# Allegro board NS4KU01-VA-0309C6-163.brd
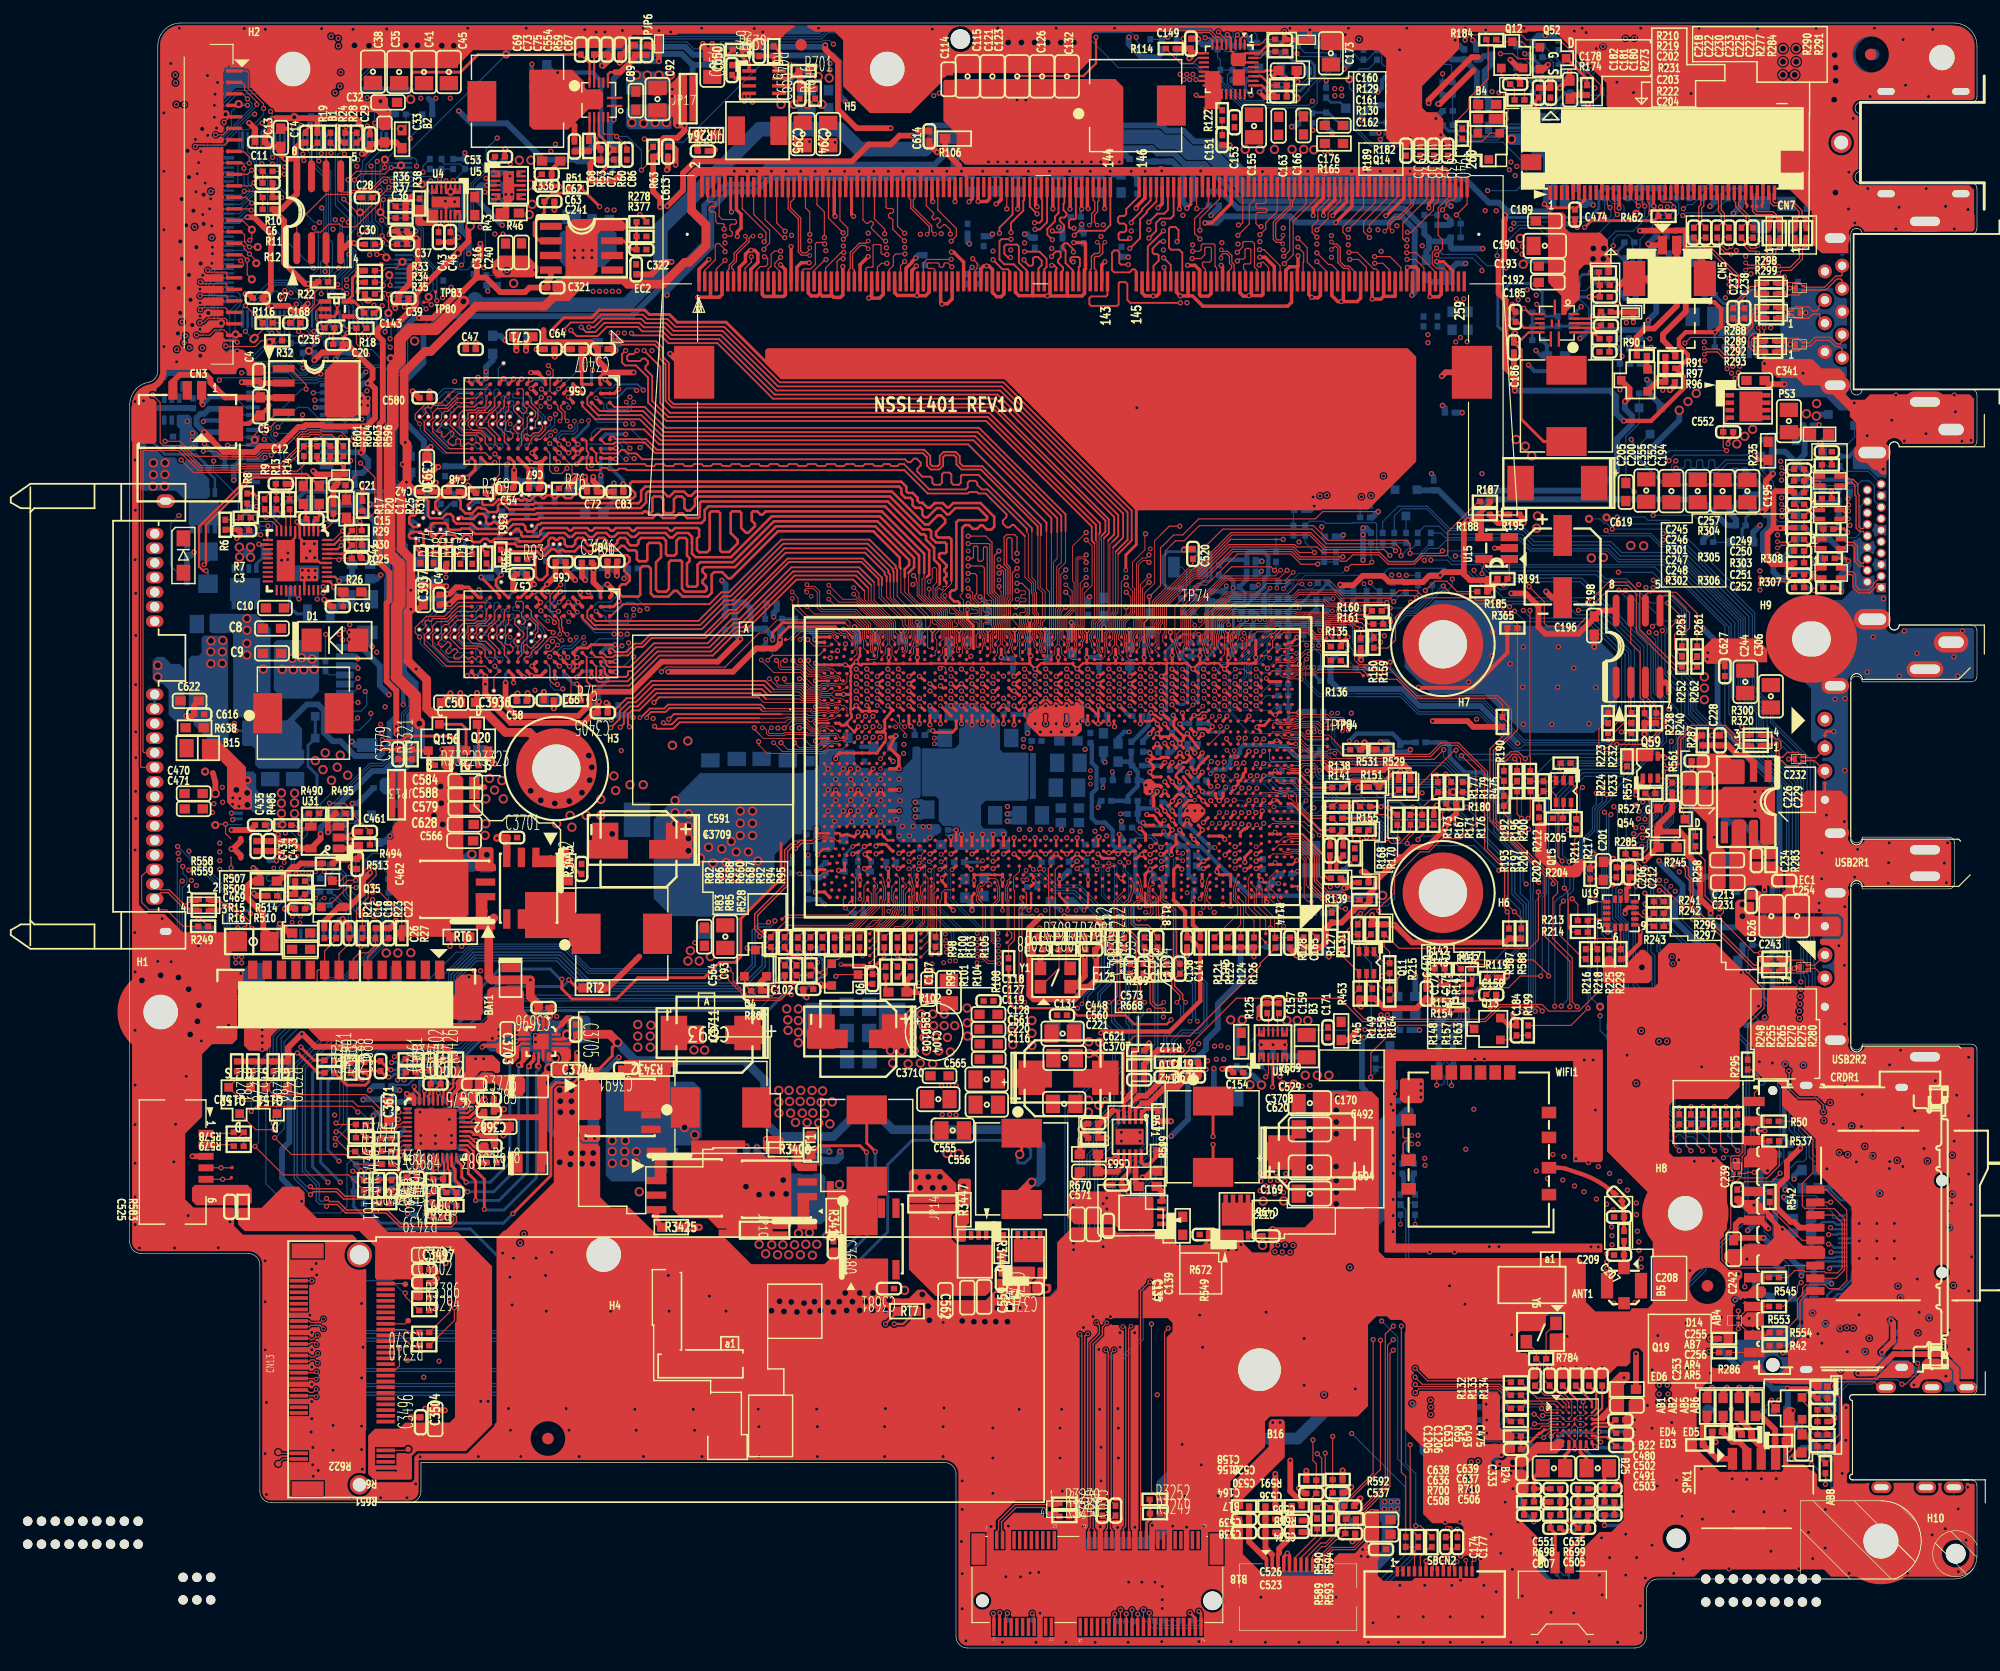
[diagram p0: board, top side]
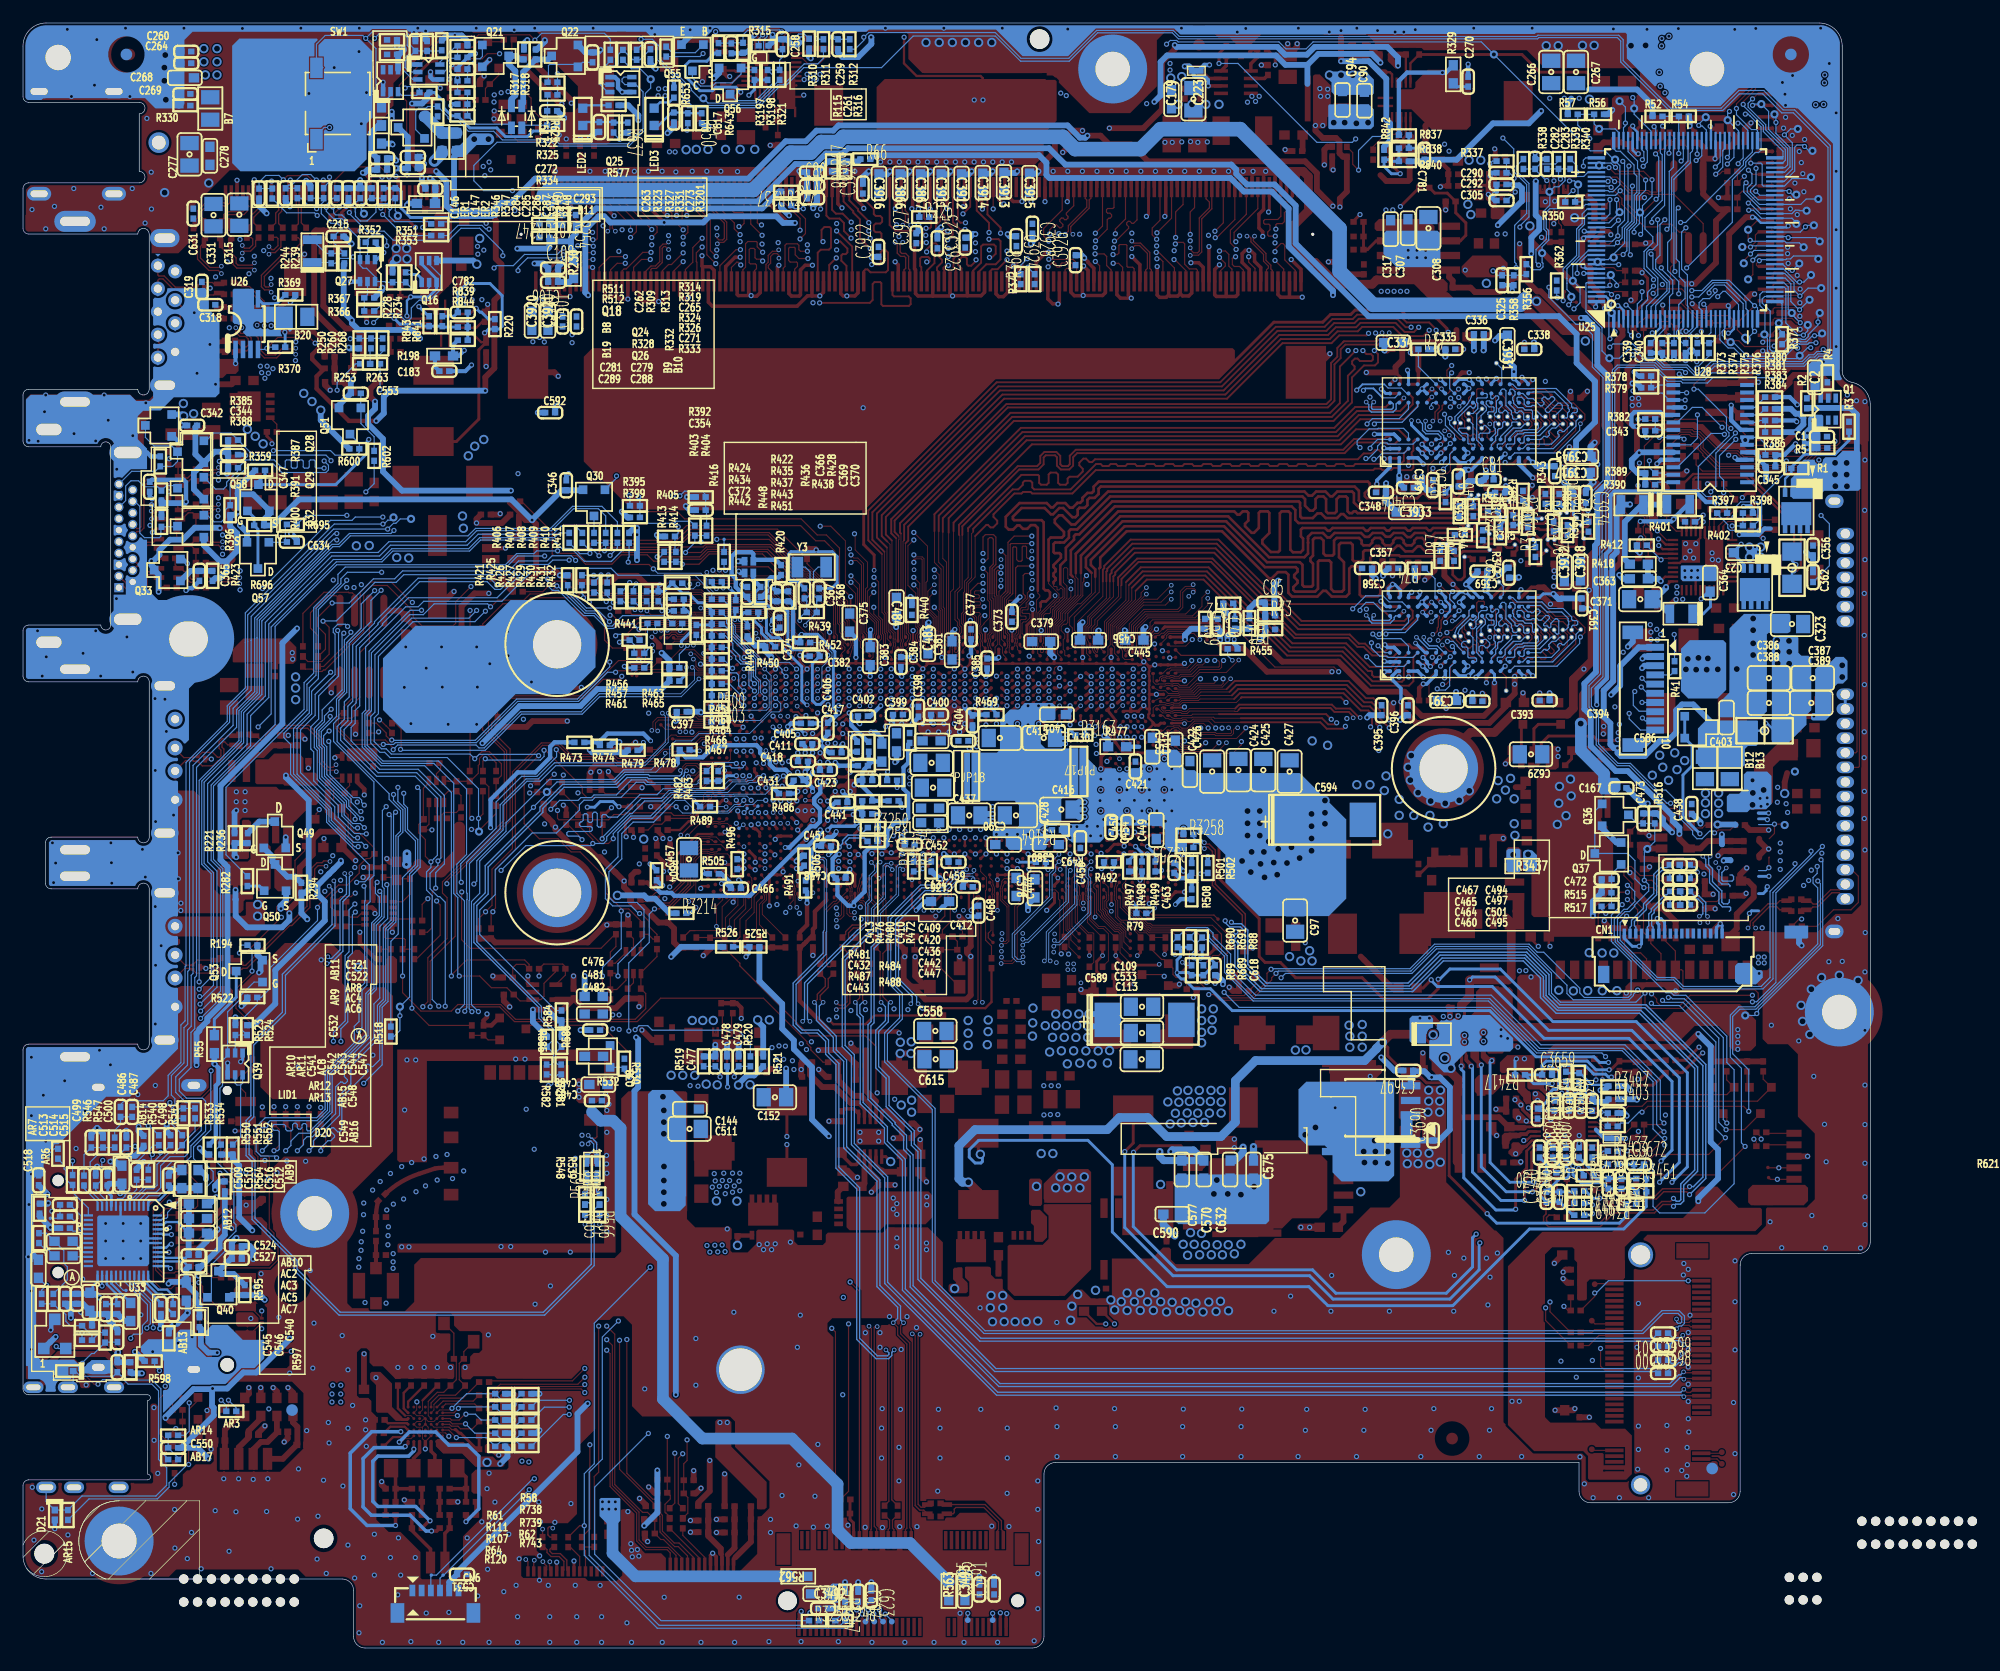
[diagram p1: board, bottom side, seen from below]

Outline 160.54 x 141.3 mm; copper layers: TOP, L2_VCC, L3_IN1, L4_IN2, L5_GND, BOTTOM. Coordinates in mm from the lower left corner of the outline.
Outline path: circle c152.19,9.3 r1.5 ; circle c158.69,8.2 r0.85 ; 153.36,6 145.19,6 145.19,12.8 152.19,12.8 ; 153.36,6 arc(155.64,9.89) 152.19,12.8 ; 153.36,6 arc(155.64,9.89) 152.19,12.8 ; 149.54,6 145.19,10.35 ; 153.1,6 146.3,12.8 ; 149.87,12.8 155.18,7.49 153.66,9.01 ; 155.26,10.98 153.87,12.37 ; 157.84,8.2 156.92,9.12 159.61,6.43 ; 160.21,6.9 arc(156.72,8.51) 160.54,8.96 ; 160.54,7.88 158.26,10.15 ; 0,108.1 arc(0.46,109.37) 1.63,110.06 arc(2.21,110.41) 2.44,111.04 2.44,139.3 arc(3.03,140.71) 4.44,141.3 158.54,141.3 arc(159.95,140.71) 160.54,139.3 160.54,134.9 arc(160.39,134.55) 160.04,134.4 150.44,134.4 arc(149.94,133.9) 150.44,133.4 150.44,128.4 arc(149.94,127.9) 150.44,127.4 160.04,127.4 arc(160.39,127.25) 160.54,126.9 160.54,123.45 arc(160.39,123.1) 160.04,122.95 150.57,122.95 150.52,123.17 150.38,123.34 150.18,123.44 149.96,123.44 149.76,123.34 149.62,123.17 149.57,122.95 149.57,109.45 149.62,109.23 149.76,109.06 149.96,108.96 150.18,108.96 150.38,109.06 150.52,109.23 150.57,109.45 160.04,109.45 arc(160.39,109.3) 160.54,108.95 160.54,104.95 arc(160.39,104.6) 160.04,104.45 153.78,104.45 arc(153.35,104.88) 152.92,104.45 152.92,88.95 arc(153.35,88.52) 153.78,88.95 160.04,88.95 arc(160.39,88.8) 160.54,88.45 160.54,84.51 arc(160.39,84.16) 160.04,84.01 150.57,84.01 arc(150.07,84.51) 149.57,84.01 149.57,70.51 arc(150.07,70.01) 150.57,70.51 158.09,70.51 arc(158.44,70.36) 158.59,70.01 158.59,66.51 arc(158.44,66.16) 158.09,66.01 150.57,66.01 arc(150.07,66.51) 149.57,66.01 149.57,52.51 arc(150.07,52.01) 150.57,52.51 160.04,52.51 arc(160.39,52.36) 160.54,52.01 160.54,22.52 arc(160.39,22.17) 160.04,22.02 149.71,22.02 arc(149.46,21.77) 149.71,21.52 149.71,15.12 arc(149.46,14.87) 149.71,14.62 160.04,14.62 arc(160.39,14.47) 160.54,14.12 160.54,8 arc(159.95,6.59) 158.54,6 132.81,6 arc(132.1,5.71) 131.81,5 131.81,1 arc(131.52,0.29) 130.81,0 72.81,0 arc(72.1,0.29) 71.81,1 71.81,15.13 arc(71.52,15.84) 70.81,16.13 25.31,16.13 25.31,13.63 arc(25.02,12.92) 24.31,12.63 12.31,12.63 arc(11.6,12.92) 11.31,13.63 11.31,33.3 arc(11.02,34.01) 10.31,34.3 1,34.3 arc(0.29,34.59) 0,35.3 0,108.1

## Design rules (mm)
constraint set DEFAULT: min track width 0.102
net group A_SPK_L: nets SPK_L+ SPK_L-
net group A_SPK_R: nets SPK_R+ SPK_R-
net group A_SPKL1: nets SPKL1+ SPKL1-
net group A_SPKR1: nets SPKR1+ SPKR1-
net group DIFFPAIR447: nets M_A_DQS5 M_A_DQS#5
net group DIFFPAIR449: nets M_A_DQS6 M_A_DQS#6
net group DIFFPAIR450: nets M_A_DQS7 M_A_DQS#7
net group DIFFPAIR460: nets M_B_DQS1 M_B_DQS#1
net group DIFFPAIR461: nets M_B_DQS0 M_B_DQS#0
net group DIFFPAIR462: nets M_B_DQS2 M_B_DQS#2
net group DIFFPAIR463: nets M_B_DQS3 M_B_DQS#3
net group DIFFPAIR464: nets M_B_DQS4 M_B_DQS#4
net group DIFFPAIR465: nets M_B_DQS5 M_B_DQS#5
net group DIFFPAIR466: nets M_B_DQS6 M_B_DQS#6
net group DIFFPAIR467: nets M_B_DQS7 M_B_DQS#7
net group DIFFPAIR472: nets USB30_RX_N_IN USB30_RX_P_IN
net group DIFFPAIR486: nets VCORE_VCCSENSE VCORE_VSSSENSE
net group DIFFPAIR487: nets VCCGTX_SENSE VSSGTX_SENSE
net group DIFFPAIR488: nets VCCGT_SENSE VSSGT_SENSE
net group DIFFPAIR489: nets VCCSA_SENSE VSSSA_SENSE
net group DIFFPAIR491: nets USB_PN8 USB_PP8
net group DIFFPAIR492: nets USB_PN5 USB_PP5
net group DIFFPAIR493: nets USB_PN7 USB_PP7
net group DIFFPAIR495: nets USB_PN6 USB_PP6
net group DIFFPAIR497: nets USB30_TX_N USB30_TX_P
net group DIFFPAIR498: nets EDP_TXN0 EDP_TXP0
net group DIFFPAIR499: nets EDP_TXN1 EDP_TXP1
net group DIFFPAIR500: nets USB30_RX_N USB30_RX_P
net group DIFFPAIR503: nets USB_PN4 USB_PP4
net group DIFFPAIR505: nets HDMIOUT_CLK+ HDMIOUT_CLK-
net group DIFFPAIR506: nets HDMIOUT_D0+ HDMIOUT_D0-
net group DIFFPAIR507: nets HDMIOUT_D1+ HDMIOUT_D1-
net group DIFFPAIR508: nets HDMIOUT_D2+ HDMIOUT_D2-
net group DIFFPAIR509: nets TMDSB_D2+_C TMDSB_D2-_C
net group DIFFPAIR510: nets TMDSB_D1+_C TMDSB_D1-_C
net group DIFFPAIR511: nets TMDSB_D0+_C TMDSB_D0-_C
net group DIFFPAIR512: nets TMDSB_CLK+_C TMDSB_CLK-_C
net group DIFFPAIR513: nets TP_USB_PN1_R TP_USB_PP1_R
net group DIFFPAIR516: nets USB30_TX_N_C USB30_TX_P_C
net group DIFFPAIR517: nets EDP_AUXN EDP_AUXP
net group DIFFPAIR518: nets EDP_AUXN_R EDP_AUXP_R
net group DIFFPAIR529: nets USB_PN4_CN_R USB_PP4_CN_R
net group DIFFPAIR530: nets PCIE_TXN11_C PCIE_TXP11_C
net group DIFFPAIR531: nets PCIE_TXN11 PCIE_TXP11
net group DIFFPAIR532: nets N28034570 N28034572
net group DIFFPAIR533: nets SATA_TXN2 SATA_TXP2
net group DIFFPAIR534: nets N28025825 N28025828
net group DIFFPAIR535: nets PCIE_TXN6 PCIE_TXP6
net group DIFFPAIR536: nets CLK_PCIE_SSD_DN CLK_PCIE_SSD_DP
net group DIFFPAIR537: nets PCIE_RXN11 PCIE_RXP11
net group DIFFPAIR538: nets PCIE_RXN6 PCIE_RXP6
net group DIFFPAIR539: nets N28022853 N28022855
net group DIFFPAIR540: nets CLK_PCIE_WLAN_DN CLK_PCIE_WLAN_DP
net group DIFFPAIR541: nets N28033617 N28033619
net group DIFFPAIR542: nets SATA_RXN2 SATA_RXP2
net group DIFFPAIR543: nets N28033621 N28033623
net group DIFFPAIR545: nets USB_PN2_LGA USB_PP2_LGA
net group DIFFPAIR546: nets USB_PN2_W USB_PP2_W
net group SATA_RXN0_R: nets SATA_RXN0_R SATA_RXP0_R
net group SATA_TXP0_R: nets SATA_TXN0_R SATA_TXP0_R
net group 85_OHM: nets CLK_PCIE_LAN_DN3 CLK_PCIE_LAN_DP3 D+_M D-_M E-USB-N E-USB-P LAN_TXN LAN_TXP PCIE_RXN10 PCIE_RXP10 PCIE_TXN10 PCIE_TXN10_C PCIE_TXP10 PCIE_TXP10_C SATA_RXN0 SATA_RXN0_C SATA_RXP0 SATA_RXP0_C SATA_TXN0 SATA_TXN0_C SATA_TXP0 SATA_TXP0_C TMDSB_CLK+ TMDSB_CLK- TMDSB_D0+ TMDSB_D0- TMDSB_D1+ TMDSB_D1- TMDSB_D2+ TMDSB_D2- USB30_TX_N_IN USB30_TX_P_IN USB_PN1 USB_PN2 USB_PP1 USB_PP2 WEBCAM_USB+ WEBCAM_USB-
net group DDR_A_D0: nets M_A_DQ0 M_A_DQ1 M_A_DQ2 M_A_DQ3 M_A_DQ4 M_A_DQ5 M_A_DQ6 M_A_DQ7 M_A_DQS0 M_A_DQS#0
net group DDR_A_D1: nets M_A_DQ8 M_A_DQ9 M_A_DQ10 M_A_DQ11 M_A_DQ12 M_A_DQ13 M_A_DQ14 M_A_DQ15 M_A_DQS1 M_A_DQS#1
net group DDR_A_D2: nets M_A_DQ16 M_A_DQ17 M_A_DQ18 M_A_DQ19 M_A_DQ20 M_A_DQ21 M_A_DQ22 M_A_DQ23
net group DDR_A_D3: nets M_A_DQ24 M_A_DQ25 M_A_DQ26 M_A_DQ27 M_A_DQ28 M_A_DQ29 M_A_DQ30 M_A_DQ31 M_A_DQS3 M_A_DQS#3
net group DDR_A_D5: nets M_A_DQ40 M_A_DQ41 M_A_DQ42 M_A_DQ43 M_A_DQ44 M_A_DQ45 M_A_DQ46 M_A_DQ47
net group DDR_A_D6: nets M_A_DQ48 M_A_DQ49 M_A_DQ50 M_A_DQ51 M_A_DQ52 M_A_DQ53 M_A_DQ54 M_A_DQ55
net group DDR_B_CMD: nets DDR1_B_ALERT# DDR1_B_PARITY M_B_ACT#
net group DIFFPAIR480: nets MB_CLK0
net group L_DDR_A_D4: nets M_A_DQ32 M_A_DQ33 M_A_DQ34 M_A_DQ35 M_A_DQ36 M_A_DQ37 M_A_DQ38 M_A_DQ39 M_A_DQS#4
net group L_DDR_A_D7: nets M_A_DQ56 M_A_DQ57 M_A_DQ58 M_A_DQ59 M_A_DQ60 M_A_DQ61 M_A_DQ62 M_A_DQ63
net group L_DDR_A_DQS: nets M_A_DQS4
net group L_DDR_B_CLK/CMD: nets M_B_A0 M_B_A1 M_B_A2 M_B_A3 M_B_A4 M_B_A5 M_B_A6 M_B_A7 M_B_A8 M_B_A9 M_B_A10_AP M_B_A11 M_B_A12 M_B_A13 M_B_A14_MB_WE# M_B_A15_MB_CAS# M_B_A16_MB_RAS# M_B_BA0 M_B_BA1 M_B_BG0 M_B_BG1
net group L_DDR_B_CLK/CTRL: nets MB_CKE0 MB_CKE1 MB_CLK1 MB_CLK#0 MB_CLK#1 MB_CS#0 MB_CS#1 MB_ODT0 MB_ODT1
net group L_DDR_B_D0: nets M_B_DQ0 M_B_DQ1 M_B_DQ2 M_B_DQ3 M_B_DQ4 M_B_DQ5 M_B_DQ6 M_B_DQ7
net group L_DDR_B_D1: nets M_B_DQ8 M_B_DQ9 M_B_DQ10 M_B_DQ11 M_B_DQ12 M_B_DQ13 M_B_DQ14 M_B_DQ15
net group L_DDR_B_D2: nets M_B_DQ16 M_B_DQ17 M_B_DQ18 M_B_DQ19 M_B_DQ20 M_B_DQ21 M_B_DQ22 M_B_DQ23
net group L_DDR_B_D3: nets M_B_DQ24 M_B_DQ25 M_B_DQ26 M_B_DQ27 M_B_DQ28 M_B_DQ29 M_B_DQ30 M_B_DQ31
net group L_DDR_B_D4: nets M_B_DQ32 M_B_DQ33 M_B_DQ34 M_B_DQ35 M_B_DQ36 M_B_DQ37 M_B_DQ38 M_B_DQ39
net group L_DDR_B_D5: nets M_B_DQ40 M_B_DQ41 M_B_DQ42 M_B_DQ43 M_B_DQ44 M_B_DQ45 M_B_DQ46 M_B_DQ47
net group L_DDR_B_D6: nets M_B_DQ48 M_B_DQ49 M_B_DQ50 M_B_DQ51 M_B_DQ52 M_B_DQ53 M_B_DQ54 M_B_DQ55
net group L_DDR_B_D7: nets M_B_DQ56 M_B_DQ57 M_B_DQ58 M_B_DQ59 M_B_DQ60 M_B_DQ61 M_B_DQ62 M_B_DQ63
net group NET_HDMI_+5V: nets HDMI_+5V
nets with their own width: min track width 0.102; nets HDMI_HPD
nets with their own width: min track width 0.254; nets +3.3VA +VCCST_CPU
nets with their own width: min track width 0.508; nets +1.00V_CPU +1.8VA_PCH +3.3V +3.3V_LCD +3.3V_WIFI +3.3VA_LDO +3.3VA_PCH +3.3VA_RTC +3.3VAL +3.3VAL_VBYP +3.3VAL_VCC +3.3VDVDD +3.3VS +5V +5V_AMP +5V_CODECAVDD +5VAL +5VAL_VCC +CPU_CORE +CPU_VCCGT +V1.00A_SIP +V1.8A_SIP +V1.8S_EDRAM +VCCAMPHYPLL_1P0 +VCCAPLL_1P0 +VCCAPLLEBB_1P0 +VCCCLKX +VCCDSW_1P0 +VCCDTS_1P0 +VCCFHV +VCCMPHYAON_1P0 +VCCMPHYAON_1P0_C +VCCMPHYGTAON_1P0_LS_SIP +VCCOPC +VCCOPC_TP +VCCPAZIO +VCCPDSW_3P3 +VCCPGPPF_1P8 +VCCPGPPX +VCCPRIM_1P0 +VCCPRIM_3P3 +VCCPRTCPRIM_3P3 +VCCPSPI +VCCSA +VCCSFR +VCCSRAM_1P0 +VCCSTG +VSDIO AGND_+1.35VS AGND_+3.3VAL AGND_+5VAL BAT_D CARD_3V3 CLICK_PAD_+3.3V CODEC_GND EC_3.3VA FAN_SPEED GND POWER GND_OZ8690 HDMI_5V_C HP_GND N20517388 PWR_B_LED_GND PWR_R_LED_GND V1.00A VIN WEBCAM_+5V

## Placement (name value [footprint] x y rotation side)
AB1  @1K-1-06  [M-R0603]  137.08 20.96 270 top
AB2  @1K-1-06  [M-R0603]  138.47 20.96 270 top
AB4  499-1-04  [M-R0402]  138.55 26.9 180 top
AB5  @1K-1-06  [M-R0603]  139.87 20.96 270 top
AB6  @1K-1-06  [M-R0603]  141.27 20.96 270 top
AB7  499-1-04  [M-R0402]  147.11 20.71 0 top
AB8  499-1-04  [M-R0402]  147.36 15.63 270 top
AB9  @1K-1-06  [M-R0603]  145.33 40.77 90 bottom
AB10  @1K-1-06  [M-R0603]  145.33 38.62 180 bottom
AB11  499-1-04  [M-R0402]  159.1 38.21 270 bottom
AB12  499-1-04  [M-R0402]  143 40.14 270 bottom
AB13  499-1-04  [M-R0402]  147.87 26.93 90 bottom
AB14  499-1-04  [M-R0402]  150.06 44.1 270 bottom
AB15  499-1-04  [M-R0402]  153.41 26.99 270 bottom
AB16  499-1-04  [M-R0402]  151.2 24.42 270 bottom
AB17  499-1-04  [M-R0402]  147.49 16.39 0 bottom
AC2  10U-6.3-06R  [M-C0603]  145.33 37.35 180 bottom
AC3  10U-6.3-06R  [M-C0603]  145.33 36.08 180 bottom
AC4  4.7U-6.3-06R-K  [M-C0603]  157.02 35.36 0 bottom
AC5  .1U-10-04R-K  [M-C0402]  145.71 34.17 180 bottom
AC6  4.7U-6.3-06R-K  [M-C0603]  157.02 34.09 0 bottom
AC7  .1U-10-04R-K  [M-C0402]  145.71 33.15 180 bottom
AC8  .1U-10-04R-K  [M-C0402]  155.87 30.36 270 bottom
ANT1  MINI-RF_RMVRN33300TP_ARGOSY  [I-PEX-20431]  129.86 31.5 270 top
AR3  499-1-04  [M-R0402]  142.44 20.58 180 bottom
AR4  499-1-04  [M-R0402]  147.11 18.55 0 top
AR5  499-1-04  [M-R0402]  147.11 17.53 180 top
AR6  499-1-04  [M-R0402]  157.5 42.98 90 bottom
AR7  499-1-04  [M-R0402]  156.23 40.69 90 bottom
AR8  499-1-04  [M-R0402]  156.89 36.51 0 bottom
AR9  499-1-04  [M-R0402]  159.15 35.64 90 bottom
AR10  499-1-04  [M-R0402]  158.92 30.36 90 bottom
AR11  499-1-04  [M-R0402]  157.91 30.36 90 bottom
AR12  499-1-04  [M-R0402]  154.97 28.02 180 bottom
AR13  499-1-04  [M-R0402]  154.98 26.77 0 bottom
AR14  499-1-04  [M-R0402]  147.49 18.5 180 bottom
AR15  499-1-04  [M-R0402]  156.64 11.56 90 bottom
AUDR1  audio_6p_santa-313072-1  [AUDIO_6P_SANTA-313072-1]  155.48 18.52 90 top
B1  499-1-04  [M-R0402]  17.44 131.33 90 top
B2  @1K-1-06  [M-R0603]  23.67 131.2 270 top
B3  @0-08  [M-R0805]  102.28 52.33 270 top
B4  @1K-1-06  [M-R0603]  117.97 134.22 180 top
B5  499-1-04  [M-R0402]  129.86 35.82 270 top
B6  -  [FCI1608]  146.86 105.54 180 top
B7  BD-HCB2012KF-120  [M-R0805]  144.27 133.87 90 bottom
B8  @1K-1-06  [M-R0603]  129.39 133.18 90 bottom
B9  @1K-1-06  [M-R0603]  124.12 130.94 90 bottom
B10  @1K-1-06  [M-R0603]  122.85 130.94 90 bottom
B11  @1K-1-06  [M-R0603]  125.52 125.61 180 bottom
B12  BD-HCB2012KF-120  [M-R0805]  14.37 76.52 90 bottom
B13  @BD-HCB2012KF-120  [M-R0805]  12.21 76.52 90 bottom
B15  0-08  [M-R0805]  5.91 78.24 0 top
B16  499-1-04  [M-R0402]  99.13 12.33 180 top
B17  499-1-04  [M-R0402]  101.42 12.36 180 top
B18  499-1-04  [M-R0402]  96.85 12.33 0 top
B19  @1K-1-06  [M-R0603]  129.39 131.6 270 bottom
B20  BD-QT2012RL-120  [M-R0805]  136.8 115.75 180 bottom
B22  @1K-1-06  [M-R0603]  130.12 22.49 180 top
B24  QTL2012-R56K-LF  [M-C0805]  123.77 15.63 180 top
B25  QTL2012-R56K-LF  [M-C0805]  127.58 15.63 0 top
BAT1  BAT_M7_TSA1-22407-00T3A_CEN  [WFN-25_14P]  18.81 58.97 0 top
C1  @.1U-10-04R-K  [M-C0402]  4.19 105.33 0 bottom
C2  VALUE*  [M-C0603]  4.79 110.49 90 bottom
C3  2.2U-6.3-04R  [M-C0402]  9.95 97.16 180 top
C4  4.7U-6.3-06R-K  [M-C0402]  11.22 110.62 90 top
C5  4.7U-6.3-06R-K  [M-C0603]  11.35 107.96 270 top
C6  .1U-10-04R-K  [M-C0402]  11.98 127.39 0 top
C7  1U-6.3-04R-K  [M-C0402]  11.12 117.38 180 top
C8  10U-25-06R  [M-C0603]  12.36 88.65 180 top
C9  10U-25-06R  [M-C0603]  12.36 86.49 180 top
C10  1U-25-06R-K  [M-C0603]  12.62 90.43 180 top
C11  .1U-10-04R-K  [M-C0402]  11.34 130.94 180 top
C12  47n-16-04X-K  [M-C0402]  13.13 101.23 0 top
C13  10U-6.3-06R  [M-C0603]  13.13 131.33 90 top
C14  @.1U-10-04R-K  [M-C0402]  15.28 131.33 90 top
C15  .1U-25-04X-K  [M-C0402]  15.79 98.18 180 top
C16  .1U-10-04R-K  [M-C0402]  17.93 62.16 90 top
C17  22P-50-04N-J  [M-C0402]  17.7 99.07 270 top
C18  .1U-10-04R-K  [M-C0402]  19.07 62.16 90 top
C19  1500P-50-04X-K  [M-C0402]  18.08 90.56 180 top
C20  1U-6.3-04R-K  [M-C0402]  18.1 113.36 180 top
C21  @1U-6.3-04R-K  [M-C0402]  18.33 101.1 0 top
C22  220P-50-04X-K  [M-C0402]  21.36 62.16 90 top
C23  @4.7U-6.3-06R-K  [M-C0603]  11.07 95.24 180 bottom
C25  1000P-50-04X-K  [M-C0402]  19.73 94.75 180 top
C26  220P-50-04X-K  [M-C0402]  22.5 62.16 90 top
C28  @.1U-10-04R-K  [M-C0402]  20.62 126.12 180 top
C29  @1U-6.3-04R-K  [M-C0402]  20.87 131.2 90 top
C30  @22P-25-04N  [M-C0402]  20.87 122.05 0 top
C32  4.7U-6.3-06R-K  [M-C0603]  22.45 134.4 180 top
C33  4.7U-6.3-06R-K  [M-C0603]  22.14 131.71 90 top
C35  22U-6.3-08R-M  [M-C0805]  23.41 137.04 90 top
C36  1U-6.3-04R-K  [M-C0402]  23.67 123.2 0 top
C37  @22P-25-04N  [M-C0402]  23.67 122.05 180 top
C38  22U-6.3-08R-M  [M-C0805]  21.14 137.07 90 top
C39  1U-6.3-04R-K  [M-C0402]  23.79 117.36 0 top
C41  22U-6.3-08R-M  [M-C0805]  25.57 137.04 90 top
C42  @2.2U-6.3-04R  [M-C0402]  25.82 100.55 0 top
C43  @2200P-50-04X-K  [M-C0402]  26.84 122.69 90 top
C45  22U-6.3-08R-M  [M-C0805]  27.73 137.04 90 top
C46  @2200P-50-04X-K  [M-C0402]  27.86 122.69 90 top
C47  2.2U-6.3-04R  [M-C0402]  29.63 112.93 0 top
C48  @2.2U-6.3-04R  [M-C0402]  28.17 100.55 180 top
C49  @2.2U-6.3-04R  [M-C0402]  26.9 91.15 90 top
C50  VALUE*  [M-C0603]  27.92 82.2 0 top
C53  2.2U-6.3-04R  [M-C0402]  32.18 129.67 180 top
C54  @2.2U-6.3-04R  [M-C0402]  32.87 100.87 180 top
C56  @2.2U-6.3-04R  [M-C0402]  38.84 112.93 0 top
C57  @2.2U-6.3-04R  [M-C0402]  34.06 93.4 0 top
C58  @2.2U-6.3-04R  [M-C0402]  34.06 82.35 180 top
C62  2200P-50-04X-K  [M-C0402]  36.24 128.15 180 top
C63  2200P-50-04X-K  [M-C0402]  36.24 127.13 180 top
C64  2.2U-6.3-04R  [M-C0402]  36.49 112.93 180 top
C65  2.2U-6.3-04R  [M-C0402]  37.45 94.45 0 top
C66  @2.2U-6.3-04R  [M-C0402]  36.41 82.41 0 top
C67  @2.2U-6.3-04R  [M-C0402]  35.14 100.83 180 top
C68  .22U-10-04R-K  [M-C0402]  38.65 130.56 90 top
C69  @.1U-10-04R-K  [M-C0402]  39.2 138.99 90 top
C71  VALUE*  [M-C0603]  34.21 114.01 180 top
C72  2.2U-6.3-04R  [M-C0402]  40.18 100.55 180 top
C73  2.2U-6.3-04R  [M-C0402]  40.35 138.99 90 top
C74  2.2U-6.3-04R  [M-C0402]  40.92 129.85 270 top
C75  .1U-10-04R-K  [M-C0402]  41.49 138.99 90 top
C76  VALUE*  [M-C0402]  56.69 89.06 270 bottom
C77  VALUE*  [M-C0402]  55.23 89.06 270 bottom
C78  VALUE*  [M-C0402]  91.97 126.03 180 bottom
C79  VALUE*  [M-C0402]  91.97 128.32 0 bottom
C80  VALUE*  [M-C0402]  91.97 127.18 180 bottom
C81  VALUE*  [M-C0402]  33.17 101.59 180 bottom
C82  VALUE*  [M-C0402]  31.41 93.5 90 bottom
C83  2.2U-6.3-04R  [M-C0402]  42.46 100.55 0 top
C84  2.2U-6.3-04R  [M-C0402]  41.95 94.5 180 top
C85  VALUE*  [M-C0402]  52.22 90.92 180 bottom
C86  .1U-10-04R-K  [M-C0402]  43.2 129.85 270 top
C87  @.1U-10-04R-K  [M-C0402]  44.94 138.95 90 top
C89  @1U-25-06R-K  [M-C0603]  43.99 134.55 90 top
C90  1U-25-06R-K  [M-C0603]  43.96 134.54 90 bottom
C92  4.7U-25-08R-K  [M-C0805]  45.87 134.68 90 top
C93  22U-6.3-08R-M  [M-C0805]  51.76 61.86 270 top
C94  @10U-25-06R  [M-C0603]  45.87 134.61 90 bottom
C97  22U-6.3-08R-M  [M-C0805]  49.98 63.26 270 bottom
C102  .1U-10-04R-K  [M-C0402]  58.97 57.28 0 top
C104  @22U-6.3-08R-M  [M-C0805]  71.19 57.03 90 top
C105  10U-6.3-06R  [M-C0603]  69.41 57.29 90 top
C106  VALUE*  [M-C0402]  114.47 118.77 0 bottom
C107  1U-6.3-04R-K  [M-C0402]  64.56 58.17 90 top
C108  VALUE*  [M-C0402]  114.47 119.98 180 bottom
C109  @22U-6.3-08R-M  [M-C0805]  63.29 55.76 180 bottom
C113  22U-6.3-08R-M  [M-C0805]  63.32 51.19 180 bottom
C114  4.7U-6.3-06R-K  [M-C0603]  71.16 136.41 90 top
C115  22U-6.3-08R-M  [M-C0805]  72.82 136.66 90 top
C116  @22U-6.3-08R-M  [M-C0805]  74.49 47.25 180 top
C118  @2.2U-6.3-04R  [M-C0402]  74.64 56.27 0 top
C119  10U-6.3-06R  [M-C0603]  74.63 53.8 180 top
C121  22U-6.3-08R-M  [M-C0805]  74.97 136.66 90 top
C123  22U-6.3-08R-M  [M-C0805]  77.13 136.66 90 top
C125  15P-50-04N-J  [M-C0402]  78.91 60.71 180 top
C126  22U-6.3-08R-M  [M-C0805]  79.29 136.66 90 top
C127  10U-6.3-06R  [M-C0603]  74.63 55.1 180 top
C128  10U-6.3-06R  [M-C0603]  74.65 52.52 180 top
C131  2.2U-6.3-04R  [M-C0402]  81.02 55.03 180 top
C132  22U-6.3-08R-M  [M-C0805]  81.45 136.66 90 top
C133  15P-50-04N-J  [M-C0402]  83.48 60.71 0 top
C134  @.1U-10-04R-K  [M-C0402]  78.43 66.18 0 bottom
C135  10U-25-06R  [M-C0603]  83.77 36.84 270 top
C136  @10U-6.3-06R  [M-C0603]  80.84 64.91 180 bottom
C137  10U-25-06R  [M-C0603]  82.37 36.84 270 top
C138  @.1U-10-04R-K  [M-C0402]  88.18 61.35 90 top
C139  .1U-25-04X-K  [M-C0402]  85.04 36.71 270 top
C140  @.1U-10-04R-K  [M-C0402]  112.69 56.9 90 top
C141  @.1U-10-04R-K  [M-C0402]  89.33 61.35 90 top
C142  @220P-50-04X-K  [M-C0402]  87.73 49.41 180 top
C143  @.1U-10-04R-K  [M-C0402]  20.77 116.08 0 top
C144  4.7U-6.3-06R-K  [M-C0603]  102.59 46.87 0 bottom
C145  .1U-10-04R-K  [M-C0402]  91.89 61.35 90 top
C146  15P-50-04N-J  [M-C0402]  140.03 126.47 270 bottom
C147  15P-50-04N-J  [M-C0402]  137.72 126.5 270 bottom
C149  1U-6.3-04R-K  [M-C0402]  92.22 139.5 90 top
C150  @.1U-10-04R-K  [M-C0402]  118.32 56.82 0 top
C151  1000P-50-04X-K  [M-C0402]  94.94 131.12 270 top
C152  @22U-6.3-08R-M  [M-C0805]  95.2 47.89 180 bottom
C153  .1U-25-04X-K  [M-C0402]  96.01 132.67 270 top
C154  2.2U-6.3-04R  [M-C0402]  96.34 50.05 0 top
C155  4.7U-25-08R-K  [M-C0805]  97.71 132.34 270 top
C156  @4.7U-6.3-06R-K  [M-C0603]  108.79 9.89 180 top
C157  @2200P-50-04X-K  [M-C0402]  98.85 55.63 270 top
C158  @10U-6.3-06R  [M-C0603]  108.79 11.16 180 top
C159  @2200P-50-04X-K  [M-C0402]  99.87 55.63 270 top
C160  .033U-16-04X-K  [M-C0402]  99.97 139.88 0 top
C161  10U-6.3-06R  [M-C0603]  100.63 137.16 180 top
C162  .1U-25-04X-K  [M-C0402]  100.12 134.88 0 top
C163  @10U-25-06R  [M-C0603]  99.84 132.36 270 top
C164  @.1U-10-04R-K  [M-C0402]  108.74 8.58 180 top
C165  @1000P-50-04X-K  [M-C0402]  100.83 61.32 90 top
C166  @10U-25-06R  [M-C0603]  102 132.39 270 top
C167  @1U-6.3-04R-K  [M-C0402]  21.62 74.79 180 bottom
C168  @.1U-10-04R-K  [M-C0402]  14.38 115.22 0 top
C169  @22U-6.3-08R-M  [M-C0805]  102.56 39.51 0 top
C170  22U-6.3-08R-M  [M-C0805]  102.56 47.38 0 top
C171  @.1U-10-04R-K  [M-C0402]  104.14 53.53 270 top
C172  1U-6.3-04R-K  [M-C0402]  104.31 69.35 90 top
C173  22U-6.3-08R-M  [M-C0805]  104.39 138.67 90 top
C174  @.1U-10-04R-K  [M-C0402]  114.37 9.21 90 top
C175  1U-6.3-04R-K  [M-C0402]  105.45 69.35 90 top
C176  4.7U-6.3-06R-K  [M-C0603]  104.64 132.39 180 top
C177  @.1U-10-04R-K  [M-C0402]  115.39 9.21 90 top
C178  1U-6.3-04R-K  [M-C0402]  120.4 135.98 0 top
C179  VALUE*  [M-C0603]  60.73 134.67 90 bottom
C180  1U-25-06R-K  [M-C0603]  125.18 135.51 90 top
C181  @.1U-25-04X-K  [M-C0402]  123.46 135.24 90 top
C182  @220P-50-04X-K  [M-C0402]  122.45 135.24 270 top
C183  1000P-50-04X-K  [M-C0402]  123.92 111.03 180 bottom
C184  .1U-10-04R-K  [M-C0402]  120.52 53.7 270 top
C185  4.7U-6.3-04X-M  [M-C0402]  120.42 115.75 90 top
C186  @.1U-10-04R-K  [M-C0402]  120.29 113.08 270 top
C189  @10U-25-06R  [M-C0603]  122.98 124.09 180 top
C190  4.7U-25-08R-K  [M-C0805]  122.98 121.93 180 top
C192  @1U-25-06R-K  [M-C0603]  123.23 118.75 180 top
C193  1U-25-06R-K  [M-C0603]  123.23 120.15 180 top
C194  22U-6.3-08R-M  [M-C0805]  138.43 100.6 270 top
C195  22U-6.3-08R-M  [M-C0805]  140.59 100.6 270 top
C196  @PY-220U-6.3  [SCE6_3X5_8MM]  124.53 94.04 180 top
C198  4.7U-6.3-06R-K  [M-C0603]  127.28 88.9 270 top
C200  22U-6.3-08R-M  [M-C0805]  131.8 100.64 270 top
C201  @4.7U-6.3-06R-K  [M-C0603]  128.06 67.57 90 top
C202  @.1U-10-04R-K  [M-C0402]  128.19 117.48 0 top
C203  2.2U-6.3-04R  [M-C0402]  128.29 114.99 0 top
C204  .22U-10-04R-K  [M-C0402]  128.17 112.7 180 top
C205  4.7U-6.3-06R-K  [M-C0603]  130.02 100.52 270 top
C206  @.1U-10-04R-K  [M-C0402]  129.2 67.44 90 top
C207  0-04  [M-C0402]  129.37 39.17 315 top
C208  @10p-50-04X-K  [M-C0402]  129.43 37.47 180 top
C209  AZ5325-01F  [M-C0402]  129.43 34.17 180 top
C212  @.1U-10-04R-K  [M-C0402]  130.35 67.44 90 top
C213  @4.7U-6.3-06R-K  [M-C0603]  138.83 68.51 180 top
C214  1U-25-06R-K  [M-C0603]  74.25 30.53 270 top
C215  .1U-10-04R-K  [M-C0402]  133.12 122.74 180 bottom
C218  .1U-10-04R-K  [M-C0402]  135.93 123.07 90 top
C220  22U-6.3-08R-M  [M-C0805]  74.47 49.44 180 top
C221  @22U-6.3-08R-M  [M-C0805]  81.21 47.31 0 top
C222  .1U-10-04R-K  [M-C0402]  136.95 123.07 90 top
C223  VALUE*  [M-C0805]  58.82 134.67 90 bottom
C225  .1U-10-04R-K  [M-C0402]  140.07 123.07 90 top
C226  4.7U-6.3-06R-K  [M-C0603]  135.53 74.73 270 top
C227  .1U-10-04R-K  [M-C0402]  141.08 123.07 90 top
C228  .1U-16-04Y-Z  [M-C0402]  138.2 78.92 270 top
C229  1U-25-06R-K  [M-C0603]  136.93 74.73 270 top
C230  .1U-10-04R-K  [M-C0402]  137.97 123.07 90 top
C231  4.7U-6.3-06R-K  [M-C0603]  138.88 66.56 180 top
C232  .1U-16-04Y-Z  [M-C0402]  136.17 77.14 180 top
C233  .1U-10-04R-K  [M-C0402]  138.98 123.07 90 top
C234  27P-50-04N-J  [M-C0402]  141.37 68.51 90 top
C235  @.1U-10-04R-K  [M-C0402]  17.36 114.8 0 top
C236  VALUE*  [M-C0402]  49.81 130.16 0 top
C237  .1U-10-04R-K  [M-C0402]  139.35 116.07 90 top
C238  .1U-10-04R-K  [M-C0402]  140.35 116.07 90 top
C239  @100P-50-04N-J  [M-C0402]  139.7 39.42 90 top
C240  4.7U-6.3-06R-K  [M-C0603]  34.05 121.35 270 top
C241  .1U-16-04Y-Z  [M-C0402]  36.47 125.78 180 top
C242  4.7U-6.3-06R-K  [M-C0603]  139.39 34.68 90 top
C243  22U-6.3-08R-M  [M-C0805]  142.67 63.63 90 top
C244  22U-6.3-08R-M  [M-C0805]  140.41 84.01 90 top
C245  .1U-10-04R-K  [M-C0402]  145.08 102.5 0 top
C246  .1U-10-04R-K  [M-C0402]  145.08 101.48 0 top
C247  .1U-10-04R-K  [M-C0402]  145.08 99.45 0 top
C248  .1U-10-04R-K  [M-C0402]  145.08 98.43 0 top
C249  .1U-10-04R-K  [M-C0402]  145.08 96.4 0 top
C250  .1U-10-04R-K  [M-C0402]  145.08 95.38 0 top
C251  .1U-10-04R-K  [M-C0402]  145.08 93.35 0 top
C252  .1U-10-04R-K  [M-C0402]  145.08 92.21 0 top
C253  @4.7U-10-06R-K  [M-C0603]  145.33 17.79 270 top
C254  22U-6.3-08R-M  [M-C0805]  144.9 63.64 90 top
C255  @.1U-10-04R-K  [M-C0402]  147.11 21.72 0 top
C256  100P-50-04N-J  [M-C0402]  147.11 19.69 0 top
C257  @.1U-10-04R-K  [M-C0402]  147.49 104.02 180 top
C258  @.1U-10-04R-K  [M-C0402]  94.53 139.45 90 bottom
C259  @.1U-10-04R-K  [M-C0402]  89.71 139.45 270 bottom
C260  .01U-25-04X-K  [M-C0402]  146.35 138.82 0 bottom
C261  820P-50-04X-K  [M-C0402]  98.98 139.09 90 bottom
C262  1000P-50-04X-K  [M-C0402]  126.44 139.3 90 bottom
C263  @.1U-10-04R-K  [M-C0402]  111.04 138.31 90 bottom
C264  1000P-50-04X-K  [M-C0402]  146.35 137.8 0 bottom
C265  @.1U-10-04R-K  [M-C0402]  122.35 137.29 0 bottom
C266  @22U-6.3-08R-M  [M-C0805]  27.73 137.04 90 bottom
C267  @22U-6.3-08R-M  [M-C0805]  25.57 137.04 90 bottom
C268  1U-25-06R-K  [M-C0603]  146.48 136.53 0 bottom
C269  @.18P-50-04N-J  [M-C0402]  146.43 135.14 180 bottom
C270  1000P-50-04X-K  [M-C0402]  34.95 136.2 90 bottom
C271  .1U-10-04R-K  [M-C0402]  122.35 134.25 0 bottom
C272  .1U-10-04R-K  [M-C0402]  114.55 133.66 180 bottom
C273  1U-6.3-04R  [M-C0402]  106.01 138.58 270 bottom
C277  4.7U-25-08R-K  [M-C0805]  146.07 129.88 270 bottom
C278  1U-25-06R-K  [M-C0603]  144.29 129.75 270 bottom
C279  1000P-50-04X-K  [M-C0402]  126.66 129.67 180 bottom
C281  @1U-6.3-04R-K  [M-C0402]  129.33 129.55 180 bottom
C282  .1U-10-04R-K  [M-C0402]  29.13 129.04 90 bottom
C283  .1U-10-04R-K  [M-C0402]  28.11 129.04 90 bottom
C284  1U-6.3-04R-K  [M-C0402]  133.27 126.5 90 bottom
C285  @100P-50-04N-J  [M-C0402]  132.25 126.5 90 bottom
C286  @.1U-10-04R-K  [M-C0402]  131.24 126.5 90 bottom
C287  @.1U-10-04R-K  [M-C0402]  130.22 126.5 90 bottom
C288  .1U-10-04R-K  [M-C0402]  126.66 128.66 180 bottom
C289  2.2U-6.3-04R  [M-C0402]  129.33 128.53 180 bottom
C290  .1U-10-04R-K  [M-C0402]  32.05 128.28 0 bottom
C292  2.2U-6.3-04R  [M-C0402]  32.05 127.26 180 bottom
C293  @.1U-10-04R-K  [M-C0402]  125.14 126.88 0 bottom
C294  VALUE*  [M-C0805]  60.71 131.64 270 top
C295  VALUE*  [M-C0805]  58.48 131.64 270 top
C305  .1U-10-04R-K  [M-C0402]  32.05 125.86 0 bottom
C306  22U-6.3-08R-M  [M-C0805]  142.62 82.75 90 top
C307  10U-6.3-06R  [M-C0603]  40.18 123.45 270 bottom
C308  @22U-6.3-08R-M  [M-C0805]  38.4 123.45 270 bottom
C315  22U-6.3-08R-M  [M-C0805]  141.74 124.63 90 bottom
C316  1U-25-06R-K  [M-C0603]  32.66 121.34 270 top
C317  @4.7U-6.3-06R-K  [M-C0603]  41.68 123.37 270 bottom
C318  2.2U-6.3-04R  [M-C0402]  144.26 116.8 0 bottom
C319  1U-6.3-04R-K  [M-C0402]  144.99 118.36 270 bottom
C321  .1U-16-04Y-Z  [M-C0402]  36.73 118.29 0 top
C322  27P-50-04N-J  [M-C0402]  44.47 121.59 180 top
C323  4.7U-25-08R-K  [M-C0805]  6.8 89.04 0 bottom
C325  @1000P-50-04X-K  [M-C0402]  32 118.93 90 bottom
C331  22U-6.3-08R-M  [M-C0805]  143.98 124.59 90 bottom
C332  2200P-50-04X-K  [M-C0402]  98.88 35.82 0 top
C333  .1U-16-04R-K  [M-C0402]  120.98 15.63 270 top
C334  VALUE*  [M-C0603]  41.45 113.5 180 bottom
C335  @2.2U-6.3-04R  [M-C0402]  36.49 112.93 180 bottom
C336  2.2U-6.3-04R  [M-C0402]  34.02 114.27 180 bottom
C338  2.2U-6.3-04R  [M-C0402]  29.63 112.93 0 bottom
C339  .1U-10-04R-K  [M-C0402]  19.09 113.04 270 bottom
C340  1U-6.3-04R-K  [M-C0402]  18.08 113.04 270 bottom
C341  10U-6.3-06R  [M-C0603]  141.3 110.21 0 top
C342  @.1U-10-04R-K  [M-C0402]  145.84 106.31 180 bottom
C343  @22P-50-04N-J  [M-C0402]  19.12 105.85 180 bottom
C344  .1U-10-04R-K  [M-C0402]  142.28 103.77 180 bottom
C345  @.1U-10-04R-K  [M-C0402]  8.68 102.73 0 bottom
C346  @2.2U-6.3-04R  [M-C0402]  113.33 101.1 90 bottom
C347  .1U-10-04R-K  [M-C0402]  149.52 100.97 270 bottom
C348  @2.2U-6.3-04R  [M-C0402]  42.53 100.49 0 bottom
C349  2.2U-6.3-04R  [M-C0402]  38.02 101.12 90 bottom
C351  @2.2U-6.3-04R  [M-C0402]  32.18 100.46 180 bottom
C352  22U-6.3-08R-M  [M-C0805]  136.27 100.6 270 top
C353  2.2U-6.3-04R  [M-C0402]  35.79 101.44 90 bottom
C354  @1000P-50-04X-K  [M-C0402]  101.64 98.94 180 bottom
C355  22U-6.3-08R-M  [M-C0805]  133.98 100.6 270 top
C356  @.18P-50-04N-J  [M-C0402]  4.98 95.43 90 bottom
C357  2.2U-6.3-04R  [M-C0402]  41.45 93.88 180 bottom
C358  @2.2U-6.3-04R  [M-C0402]  43.73 93.88 0 bottom
C359  2.2U-6.3-04R  [M-C0402]  33.7 93.63 0 bottom
C361  @2.2U-6.3-04R  [M-C0402]  25.06 90.83 90 bottom
C362  @.18P-50-04N-J  [M-C0402]  4.98 93.12 270 bottom
C363  1U-25-06R-K  [M-C0603]  20.11 92.97 0 bottom
C364  .47U-16-06Y-Z  [M-C0603]  13.91 92.64 270 bottom
C365  @.1U-10-04R-K  [M-C0402]  145.21 93.23 90 bottom
C366  1U-6.3-04R-K  [M-C0402]  97.58 91.83 90 bottom
C367  18P-50-04N-J  [M-C0402]  92.63 91.7 270 bottom
C368  18P-50-04N-J  [M-C0402]  91.36 91.7 270 bottom
C369  1U-6.3-04R-K  [M-C0402]  95.04 91.45 90 bottom
C370  .1U-10-04R-K  [M-C0402]  94.02 91.45 90 bottom
C371  4.7U-25-08R-K  [M-C0805]  19.98 91.19 180 bottom
C372  1U-6.3-04R-K  [M-C0402]  103.55 90.18 180 bottom
C373  @2.2U-6.3-04R  [M-C0402]  74.59 89.67 270 bottom
C374  1U-6.3-04R-K  [M-C0402]  94.79 89.16 270 bottom
C375  @10U-6.3-06R  [M-C0603]  88.69 89.16 270 bottom
C377  @2.2U-6.3-04R  [M-C0402]  78.15 88.15 90 bottom
C378  @10U-6.3-06R  [M-C0603]  72.59 66.05 90 bottom
C379  10U-6.3-06R  [M-C0603]  72.05 87.51 180 bottom
C380  @10U-6.3-06R  [M-C0603]  71.32 69.86 180 bottom
C381  10U-6.3-06R  [M-C0603]  79.8 86.75 90 bottom
C382  1U-6.3-04R-K  [M-C0402]  91.74 86.24 0 bottom
C383  10U-6.3-06R  [M-C0603]  86.91 86.24 90 bottom
C384  2.2U-6.3-04R  [M-C0402]  84.25 85.73 270 bottom
C385  2.2U-6.3-04R  [M-C0402]  76.75 85.61 270 bottom
C386  4.7U-25-08R-K  [M-C0805]  8.81 84.34 0 bottom
C387  4.7U-25-08R-K  [M-C0805]  5 84.34 180 bottom
C388  4.7U-25-08R-K  [M-C0805]  8.81 82.18 0 bottom
C389  4.7U-25-08R-K  [M-C0805]  5.12 82.18 180 bottom
C390  @10U-6.3-06R  [M-C0603]  75.26 69.86 0 bottom
C391  VALUE*  [M-C0603]  36.79 82.39 0 bottom
C393  2.2U-6.3-04R  [M-C0402]  34.14 82.32 180 bottom
C394  @2.2U-6.3-04R  [M-C0402]  28.3 82.39 0 bottom
C395  @2.2U-6.3-04R  [M-C0402]  42.46 81.54 90 bottom
C396  2.2U-6.3-04R  [M-C0402]  40.18 81.54 90 bottom
C397  1U-6.3-04R-K  [M-C0402]  103.3 81.41 180 bottom
C398  2.2U-6.3-04R  [M-C0402]  82.72 81.41 90 bottom
C399  2.2U-6.3-04R  [M-C0402]  84.5 81.16 180 bottom
C400  .1U-10-04R-K  [M-C0402]  81.2 81.16 0 bottom
C401  @10U-6.3-06R  [M-C0603]  70.68 81.16 180 bottom
C402  .1U-10-04R-K  [M-C0402]  87.55 81.03 0 bottom
C403  1U-25-06R-K  [M-C0603]  12.49 80.91 90 bottom
C404  .1U-10-04R-K  [M-C0402]  78.02 80.65 90 bottom
C405  1U-6.3-04R-K  [M-C0402]  92.5 80.4 180 bottom
C406  1U-6.3-04R-K  [M-C0402]  90.6 80.02 90 bottom
C409  10U-6.3-06R  [M-C0603]  81.58 78.87 0 bottom
C410  10U-6.3-06R  [M-C0603]  84.63 78.75 270 bottom
C411  1U-6.3-04R-K  [M-C0402]  92.37 78.62 0 bottom
C412  @.1U-10-04R-K  [M-C0402]  78.81 78.88 180 bottom
C413  1U-6.3-04R-K  [M-C0402]  88.06 78.37 90 bottom
C414  10U-6.3-06R  [M-C0603]  62.4 78.37 90 bottom
C415  @22U-6.3-08R-M  [M-C0805]  75.64 79.13 0 bottom
C416  @22U-6.3-08R-M  [M-C0805]  70.3 72.91 180 bottom
C417  1U-6.3-04R-K  [M-C0402]  89.83 77.86 180 bottom
C418  1U-6.3-04R-K  [M-C0402]  92.75 77.1 0 bottom
C420  22U-6.3-08R-M  [M-C0805]  81.58 76.97 0 bottom
C421  .1U-10-04R-K  [M-C0402]  63.86 76.65 90 bottom
C422  10U-6.3-06R  [M-C0603]  59.13 76.34 90 bottom
C423  1U-6.3-04R-K  [M-C0402]  90.85 76.33 180 bottom
C424  22U-6.3-08R-M  [M-C0805]  54.91 76.33 90 bottom
C425  22U-6.3-08R-M  [M-C0805]  52.75 76.33 90 bottom
C426  22U-6.3-08R-M  [M-C0805]  57.19 76.21 90 bottom
C427  22U-6.3-08R-M  [M-C0805]  50.46 76.21 90 bottom
C428  @22U-6.3-08R-M  [M-C0805]  74.24 72.4 0 bottom
C430  @22U-6.3-08R-M  [M-C0805]  71.83 79.13 180 bottom
C431  1U-6.3-04R-K  [M-C0402]  93.14 75.45 180 bottom
C432  1U-6.3-04R-K  [M-C0402]  87.17 75.45 0 bottom
C433  .1U-10-04R-K  [M-C0402]  12.14 69.73 270 top
C434  @1000P-25-04X-K  [M-C0402]  10.99 69.73 270 top
C435  2.2U-6.3-04R  [M-C0402]  11.33 71.56 180 top
C436  22U-6.3-08R-M  [M-C0805]  81.45 74.81 0 bottom
C437  22U-6.3-08R-M  [M-C0805]  78.3 72.4 180 bottom
C438  220P-50-04X-K  [M-C0402]  15.52 72.95 270 bottom
C441  1U-6.3-04R-K  [M-C0402]  89.33 73.54 0 bottom
C442  10U-6.3-06R  [M-C0603]  81.71 73.03 0 bottom
C443  1U-6.3-04R-K  [M-C0402]  87.17 72.52 0 bottom
C444  10U-6.3-06R  [M-C0603]  74.24 66.18 90 bottom
C445  10U-6.3-06R  [M-C0603]  63.95 87.64 0 bottom
C447  10U-6.3-06R  [M-C0603]  81.71 71.76 0 bottom
C448  @22U-6.3-08R-M  [M-C0805]  81.08 53.43 0 top
C449  10U-6.3-06R  [M-C0603]  62.05 71.13 270 bottom
C450  .1U-10-04R-K  [M-C0402]  64.59 71.38 270 bottom
C451  .1U-10-04R-K  [M-C0402]  90.75 69.73 0 bottom
C452  .1U-10-04R-K  [M-C0402]  83.48 69.86 0 bottom
C453  10U-6.3-06R  [M-C0603]  60.4 78.11 90 bottom
C454  @.1U-10-04R-K  [M-C0402]  65.99 71.38 270 bottom
C455  10U-6.3-06R  [M-C0603]  67.89 87.64 180 bottom
C456  .1U-10-04R-K  [M-C0402]  68.65 69.99 270 bottom
C457  22U-6.3-08R-M  [M-C0805]  102.66 68.59 270 bottom
C458  .1U-10-04R-K  [M-C0402]  89.48 66.94 0 bottom
C459  .1U-10-04R-K  [M-C0402]  79.67 68.33 0 bottom
C460  .01U-25-04X-K  [M-C0402]  16.96 64.62 180 bottom
C461  1U-6.3-04R-K  [M-C0402]  20.44 70.99 180 top
C462  1U-6.3-04R-K  [M-C0402]  19.77 68.17 270 top
C463  .1U-10-04R-K  [M-C0402]  60.5 67.83 270 bottom
C464  .01U-25-04X-K  [M-C0402]  16.96 65.79 180 bottom
C465  .01U-25-04X-K  [M-C0402]  16.98 66.92 180 bottom
C466  1U-6.3-04R-K  [M-C0402]  98.58 66.07 0 bottom
C467  .01U-25-04X-K  [M-C0402]  16.99 68.11 180 bottom
C468  @.1U-10-04R-K  [M-C0402]  77.49 64.12 270 bottom
C469  @.1U-10-04R-K  [M-C0402]  14.8 64.27 180 top
C470  4.7U-6.3-06R-K  [M-C0603]  5.55 74.3 0 top
C471  4.7U-6.3-06R-K  [M-C0603]  5.56 72.97 0 top
C472  @.1U-10-04R-K  [M-C0402]  22.91 66.86 0 bottom
C473  1U-6.3-04R-K  [M-C0402]  19.74 72.14 90 bottom
C474  1U-6.3-04Y-Z  [M-C0402]  125.6 124.64 90 top
C475  1U-10-04R-K  [M-C0402]  127.96 23.25 90 top
C476  4.7U-6.3-06R-K  [M-C0603]  110.94 56.65 0 bottom
C477  @.1U-10-04R-K  [M-C0402]  100.37 51.01 90 bottom
C478  2.2U-6.3-04R  [M-C0402]  99.36 51.01 270 bottom
C479  .1U-10-04R-K  [M-C0402]  98.34 51.01 90 bottom
C480  4.7U-6.3-06R-K  [M-C0603]  130.12 21.09 0 top
C481  4.7U-6.3-06R-K  [M-C0603]  110.94 55.13 0 bottom
C482  .1U-10-04R-K  [M-C0402]  110.82 53.73 0 bottom
C483  VALUE*  [M-C0603]  81.9 87.28 90 bottom
C484  VALUE*  [M-C0603]  84.63 90.52 270 bottom
C485  .1U-10-04R-K  [M-C0402]  110.66 47.6 0 bottom
C486  1U-6.3-04R-K  [M-C0402]  152.06 46.62 90 bottom
C487  1U-6.3-04R-K  [M-C0402]  151.05 46.62 90 bottom
C488  10U-6.3-06R  [M-C0603]  110.54 48.99 0 bottom
C490  1U-10-04R-K  [M-C0402]  120.47 17.28 180 top
C491  1U-10-04R-K  [M-C0402]  129.61 18.68 180 top
C492  @22U-6.3-08R-M  [M-C0805]  102.56 45.09 0 top
C493  .1U-16-04R-K  [M-C0402]  126.82 23.25 90 top
C494  @.01U-25-04X-K  [M-C0402]  16.12 68.1 0 bottom
C495  @.01U-25-04X-K  [M-C0402]  16.1 64.62 0 bottom
C496  1000P-50-04X-K  [M-C0402]  93.42 35.95 0 top
C497  @.01U-25-04X-K  [M-C0402]  16.11 66.92 0 bottom
C498  @22P-50-04N-J  [M-C0402]  147.72 44.15 270 bottom
C499  100P-50-04N-J  [M-C0402]  154.6 43.95 270 bottom
C500  @22P-50-04N-J  [M-C0402]  151.56 43.95 270 bottom
C501  @.01U-25-04X-K  [M-C0402]  16.09 65.79 0 bottom
C502  1U-10-04R-K  [M-C0402]  129.55 19.84 180 top
C503  .1U-16-04R-K  [M-C0402]  129.61 17.54 0 top
C504  @22U-6.3-08R-M  [M-C0805]  102.56 41.79 0 top
C505  1000P-50-04X-K  [M-C0402]  128.6 11.57 0 top
C506  47p-50-04N-J  [M-C0402]  126.31 10.42 0 top
C507  1000P-50-04X-K  [M-C0402]  121.61 11.57 180 top
C508  47p-50-04N-J  [M-C0402]  123.9 10.42 180 top
C509  10U-6.3-06R  [M-C0603]  151.94 41.16 90 bottom
C510  22P-50-04N-J  [M-C0402]  150.67 41.16 270 bottom
C511  @22U-6.3-08R-M  [M-C0805]  102.61 45.14 0 bottom
C512  10U-6.3-06R  [M-C0603]  146.73 40.77 90 bottom
C513  1U-6.3-04R-K  [M-C0402]  155.24 40.65 270 bottom
C514  @22P-50-04N-J  [M-C0402]  154.22 40.65 270 bottom
C515  .1U-10-04R-K  [M-C0402]  153.21 40.65 90 bottom
C516  .1U-10-04R-K  [M-C0402]  147.87 40.65 90 bottom
C517  @.1U-25-04X-K  [M-C0402]  110.45 132.26 270 bottom
C518  .1U-10-04R-K  [M-C0402]  159.18 40.67 90 bottom
C519  @.1U-10-04R-K  [M-C0402]  90.12 49.67 0 top
C520  @22P-50-04N-J  [M-C0402]  92.4 95.13 270 top
C521  @2.2U-6.3-04R  [M-C0402]  156.89 38.54 0 bottom
C522  @2.2U-6.3-04R  [M-C0402]  156.89 37.52 0 bottom
C523  @.1U-10-04R-K  [M-C0402]  99.13 10.04 0 top
C524  @2.2U-6.3-04R  [M-C0402]  141.95 34.96 180 bottom
C525  1U-6.3-04R-K  [M-C0402]  8.71 38.36 270 top
C526  @.1U-10-04R-K  [M-C0402]  99.13 11.19 0 top
C527  .1U-10-04R-K  [M-C0402]  141.95 33.82 180 bottom
C528  @.1U-10-04R-K  [M-C0402]  96.85 11.19 180 top
C529  @2200P-50-04X-K  [M-C0402]  92.4 49.67 0 top
C530  @.1U-10-04R-K  [M-C0402]  96.85 10.04 180 top
C531  @.1U-10-04R-K  [M-C0402]  122.39 6.4 0 bottom
C532  10U-6.3-06R  [M-C0603]  159.2 32.97 270 bottom
C533  @22U-6.3-08R-M  [M-C0805]  63.29 53.47 180 bottom
C534  @100P-50-04X-K1  [M-C0402]  106.07 9.96 0 top
C535  @100P-50-04X-K1  [M-C0402]  105.99 12.33 0 top
C536  @22P-50-04N-J  [M-C0402]  104.98 13.5 0 top
C537  @22P-50-04N-J  [M-C0402]  102.69 13.44 180 top
C538  @.1U-10-04R-K  [M-C0402]  101.42 10.07 0 top
C539  @.1U-10-04R-K  [M-C0402]  101.42 11.09 0 top
C540  10U-6.3-06R  [M-C0603]  146.35 31 90 bottom
C541  1000P-50-04X-K  [M-C0402]  156.89 30.36 270 bottom
C542  10U-6.3-06R  [M-C0603]  154.73 30.11 270 bottom
C543  2.2U-6.3-04R  [M-C0402]  153.33 29.47 270 bottom
C544  .1U-10-04R-K  [M-C0402]  152.32 29.47 270 bottom
C545  2.2U-6.3-04R  [M-C0402]  148.56 29.47 90 bottom
C546  2.2U-6.3-04R  [M-C0402]  147.49 29.47 270 bottom
C547  10U-6.3-06R  [M-C0603]  151.17 29.22 270 bottom
C548  220P-50-04X-K  [M-C0402]  152.32 27.03 270 bottom
C549  @.1U-10-04R-K  [M-C0402]  152.34 24.42 270 bottom
C550  100P-50-04N-J  [M-C0402]  147.49 17.41 180 bottom
C551  C_180P_50_04N_J  [M-C0402]  121.61 13.85 0 top
C552  .1U-25-04X-K  [M-C0402]  138.92 105.74 0 top
C553  2.2U-6.3-04R-K  [M-C0402]  131.62 109.1 0 bottom
C554  2.2U-6.3-04R  [M-C0402]  42.63 138.99 270 top
C555  22U-6.3-08R-M  [M-C0805]  70.27 47.72 0 top
C556  22U-6.3-08R-M  [M-C0805]  71.52 45.01 0 top
C558  22U-6.3-08R-M  [M-C0805]  81.25 53.65 0 bottom
C559  10U-25-06R  [M-C0603]  72.79 30.47 270 top
C560  @22U-6.3-08R-M  [M-C0805]  81.25 51.3 0 top
C561  4.7U-6.3-06R-K  [M-C0603]  74.65 51.2 180 top
C562  VALUE*  [M-C0603]  70.89 30.28 270 top
C563  .22U-16-04Y-Z  [M-C0402]  85.8 40.27 0 top
C564  4.7U-6.3-06R-K  [M-C0603]  49.93 61.85 270 top
C565  4.7U-6.3-06R-K  [M-C0603]  70.38 49.75 0 top
C566  1U-25-06R-K  [M-C0603]  29.06 70.18 0 top
C570  10U-25-06R  [M-C0603]  57.92 41.6 90 bottom
C571  1U-25-06R-K  [M-C0603]  83.36 41.41 180 top
C573  @2200P-50-04X-K  [M-C0402]  83.74 45.6 180 top
C575  10U-25-06R  [M-C0603]  53.6 41.6 90 bottom
C577  1U-25-06R-K  [M-C0603]  59.83 41.6 90 bottom
C579  10U-25-06R  [M-C0603]  29.17 73.01 0 top
C580  @.1U-25-04X-K  [M-C0402]  25.63 108.72 0 top
C583  -  [M-D7343]  63.32 53.6 180 top
C584  10U-25-06R  [M-C0603]  29.17 75.36 0 top
C586  2200P-50-04X-K  [M-C0402]  22.39 46.51 180 bottom
C588  10U-25-06R  [M-C0603]  29.17 74.22 0 top
C589  -  [M-D7343]  63.06 54.62 180 bottom
C590  10U-25-06R  [M-C0603]  60.65 37.73 0 bottom
C591  -  [M-D7343]  44.52 70.26 180 top
C592  @.1U-25-04X-K  [M-C0402]  114.73 107.42 180 bottom
C593  -  [M-D7343]  50.49 53.48 180 top
C594  -  [M-D7343]  47.29 72.01 180 bottom
C597  @.1U-10-04R-K  [M-C0402]  87.96 4.45 270 bottom
C613  @.1U-25-04X-K  [M-C0402]  46.76 130.12 270 top
C614  @.1U-25-04X-K  [M-C0402]  69.49 131.45 90 top
C615  22U-6.3-08R-M  [M-C0805]  81.23 51.19 0 bottom
C616  @.1U-25-04X-K  [M-C0402]  6.04 81.19 180 top
C617  @.1U-25-04X-K  [M-C0402]  103.97 133.08 270 bottom
C618  .1U-10-04R-K  [M-C0402]  56.94 58.93 270 bottom
C619  -  [M-D7343]  124.08 101.3 180 top
C620  -  [M-D7343]  103.3 43.08 0 top
C621  -  [M-D7343]  81.58 49.58 0 top
C622  @4.7U-6.3-06R-K  [M-C0603]  5.2 82.36 0 top
C623  @.1U-10-04R-K  [M-C0402]  86.81 4.58 270 bottom
C626  .1U-25-04X-K  [M-C0402]  140.92 64.96 90 top
C627  .1U-25-04X-K  [M-C0402]  138.63 84.94 90 top
C628  10U-25-06R  [M-C0603]  29.1 71.62 0 top
C629  @22U-25-08R-M  [M-C0805]  29.49 77.71 0 bottom
C631  .1U-25-04X-K  [M-C0402]  145.74 124.72 90 bottom
C632  10U-25-06R  [M-C0603]  55.64 41.6 90 bottom
C633  0-04  [M-C0402]  124.53 23.25 90 top
C634  2.2U-6.3-04R  [M-C0402]  137.18 96.17 0 bottom
C635  C_180P_50_04N_J  [M-C0402]  128.6 13.85 0 top
C636  100P-50-04N-J  [M-C0402]  123.9 12.71 0 top
C637  100P-50-04N-J  [M-C0402]  126.31 12.71 0 top
C638  27P-50-04N-J  [M-C0402]  123.9 13.85 0 top
C639  27P-50-04N-J  [M-C0402]  126.31 13.85 180 top
C649  VALUE*  [M-C0402]  54.7 138.86 90 top
C650  VALUE*  [M-C0805]  50.63 137.59 90 top
C653  VALUE*  [M-C0402]  58.23 135.16 90 top
C654  VALUE*  [M-C0402]  52.35 137.21 90 top
C693  .1U-10-04R-K  [M-C0402]  90.12 59.06 90 top
C694  .1U-10-04R-K  [M-C0402]  91.26 59.06 90 top
C695  .1U-10-04R-K  [M-C0402]  85.67 11.95 90 top
C696  .1U-10-04R-K  [M-C0402]  84.53 11.95 90 top
C781  @10n-50-04X-K  [M-C0402]  38.76 129.84 270 bottom
C782  @10n-50-04X-K  [M-C0402]  122.32 116.13 0 bottom
C1205  12P-50-04N-J  [M-C0402]  122.12 23.25 270 top
C1206  12P-50-04N-J  [M-C0402]  123.39 23.25 270 top
C3400  VALUE*  [M-C0402]  113.65 115.34 90 bottom
C3401  VALUE*  [M-C0402]  112.44 115.34 90 bottom
C3404  VALUE*  [M-C0402]  40.09 100.89 0 bottom
C3405  VALUE*  [M-C0402]  41.11 81.33 180 top
C3406  VALUE*  [M-C0402]  39.73 94.39 0 top
C3407  VALUE*  [M-C0402]  41.11 112.95 180 top
C3491  .1U-16-04R-K  [M-C0402]  76.15 5.09 90 bottom
C3492  @4.7U-6.3-06R-K  [M-C0603]  91.26 4.71 180 bottom
C3493  4.7U-6.3-06R-K  [M-C0603]  78.69 4.96 90 bottom
C3494  @.1U-16-04Y-Z  [M-C0402]  91 3.44 180 bottom
C3495  .1U-16-04R-K  [M-C0402]  77.42 5.09 90 bottom
C3496  .1U-16-04Y-Z  [M-C0402]  25.28 19.63 90 top
C3497  4.7U-6.3-06R-K  [M-C0603]  25.98 34.17 0 top
C3498  .22U-10-04R-K  [M-C0402]  18 23.89 180 bottom
C3499  .22U-10-04R-K  [M-C0402]  18 25.03 180 bottom
C3500  .22U-10-04R-K  [M-C0402]  18 26.24 0 bottom
C3501  .22U-10-04R-K  [M-C0402]  18 27.38 0 bottom
C3502  .1U-16-04Y-Z  [M-C0402]  25.6 31.76 0 top
C3503  .1U-16-04Y-Z  [M-C0402]  25.6 32.9 0 top
C3504  4.7U-6.3-06R-K  [M-C0603]  26.55 19.89 90 top
C3535  @.22U-10-04R-K  [M-C0402]  88.08 59.06 90 top
C3579  VALUE*  [M-C0402]  23.33 77.71 90 top
C3658  1000P-50-04X-K  [M-C0402]  28.91 46.47 270 bottom
C3659  22P-50-04N-J  [M-C0402]  28.09 49.83 180 bottom
C3660  1U-25-04R-K  [M-C0402]  24.16 47.14 90 bottom
C3661  1000P-50-04X-K  [M-C0402]  26.07 50.7 90 top
C3662  470P-50-04X-K  [M-C0402]  26.58 49.05 0 top
C3671  1U-16-06R-K  [M-C0603]  22.5 46.66 90 top
C3672  .1U-16-04Y-Z  [M-C0402]  20.1 42.06 180 bottom
C3673  1000P-50-04X-K  [M-C0402]  26.18 47.17 90 bottom
C3674  1000P-50-04X-K  [M-C0402]  25.18 47.14 90 bottom
C3675  .22U-16-04R-K  [M-C0402]  29.93 49.01 180 top
C3680  680P-50-04X-K  [M-C0402]  61.16 34.93 270 top
C3681  2200P-50-04X-K  [M-C0402]  65.99 31.25 180 top
C3682  1U-16-06R-K  [M-C0603]  32.15 45.33 180 top
C3683  .22U-16-04R-K  [M-C0402]  31.26 43.68 180 top
C3684  470P-50-04X-K  [M-C0402]  24.54 40.92 0 top
C3685  10n-50-04X-K  [M-C0402]  20.41 50.53 90 top
C3686  1000P-50-04X-K  [M-C0402]  25.31 43.08 90 bottom
C3687  22P-50-04N-J  [M-C0402]  26.45 43.08 90 bottom
C3688  @4700P-50-04X-K  [M-C0402]  21.8 50.6 90 top
C3689  1000P-50-04X-K  [M-C0402]  22.75 40.25 270 top
C3690  2200P-50-04X-K  [M-C0402]  37.99 44.56 90 bottom
C3691  680P-50-04X-K  [M-C0402]  43.14 50.41 180 top
C3692  1000P-50-04X-K  [M-C0402]  28.74 43.08 270 bottom
C3693  22P-50-04N-J  [M-C0402]  27.59 43.08 270 bottom
C3694  1000P-50-04X-K  [M-C0402]  26.3 39.19 90 top
C3695  470P-50-04X-K  [M-C0402]  27.96 39.61 180 top
C3696  .22U-16-04R-K  [M-C0402]  35.96 55.68 180 top
C3697  VALUE*  [M-C0402]  40.15 50.22 0 bottom
C3701  1000P-50-04X-K  [M-C0402]  33.23 70.47 0 top
C3702  680P-50-04X-K  [M-C0402]  39.26 67.74 90 top
C3703  1U-16-06R-K  [M-C0603]  32.84 52.97 270 top
C3704  1U-16-06R-K  [M-C0603]  38.12 50.28 0 top
C3705  .22U-16-04R-K  [M-C0402]  38.76 53.77 270 top
C3706  6800P-50-04X-K  [M-C0402]  27.01 39.23 90 bottom
C3707  PY-220U-6.3M  [SCE6_3X5_8MM]  81.07 49.54 270 top
C3708  PY-220U-6.3M  [SCE6_3X5_8MM]  103.17 43.19 270 top
C3709  PY-220U-6.3M  [SCE6_3X5_8MM]  44.22 69.46 90 top
C3710  PY-220U-6.3M  [SCE6_3X5_8MM]  63.32 52.97 90 top
C3711  Value*  [SCE6_3X5_8MM]  50.82 53.33 90 top
C3713  2200P-50-04X-K  [M-C0402]  78.3 31.25 180 top
C3714  680P-50-04X-K  [M-C0402]  75.76 32.14 270 top
C3715  3300P-50-04X-K  [M-C0402]  21.62 40.38 270 bottom
C3720  1000P-50-04X-K  [M-C0402]  28.15 39.23 90 bottom
C3721  @2.7N-50-04X-K  [M-C0402]  22.77 40.38 270 bottom
C3773  @16P-50-04N-J  [M-C0402]  31.21 47.78 0 top
C3783  @16P-50-04N-J  [M-C0402]  31.21 46.64 0 top
C3866  VALUE*  [M-C0603]  84.31 127.35 270 bottom
C3867  VALUE*  [M-C0603]  82.53 127.35 270 bottom
C3883  @.22U-10-04R-K  [M-C0402]  86.94 59.06 90 top
C3911  VALUE*  [M-C0603]  80.75 127.35 270 bottom
C3912  VALUE*  [M-C0603]  78.97 127.35 270 bottom
C3913  VALUE*  [M-C0603]  75.29 127.47 270 bottom
C3914  VALUE*  [M-C0603]  77.13 127.41 270 bottom
C3915  VALUE*  [M-C0603]  73.07 127.41 270 bottom
C3916  VALUE*  [M-C0603]  86.15 127.35 270 bottom
C3917  VALUE*  [M-C0603]  25.17 102.22 0 bottom
C3918  VALUE*  [M-C0603]  25.19 93.63 90 bottom
C3919  VALUE*  [M-C0402]  27.41 102.33 270 bottom
C3920  VALUE*  [M-C0603]  116.31 115.41 90 bottom
C3921  VALUE*  [M-C0603]  114.92 115.41 90 bottom
C3922  VALUE*  [M-C0402]  86.19 121.4 90 bottom
C3923  VALUE*  [M-C0402]  81.07 122.14 270 bottom
C3924  VALUE*  [M-C0402]  74.21 122.33 270 bottom
C3925  VALUE*  [M-C0402]  78.66 122.2 90 bottom
C3926  VALUE*  [M-C0402]  69.07 120.68 90 bottom
C3927  VALUE*  [M-C0402]  82.91 122.58 90 bottom
C3928  VALUE*  [M-C0402]  72.81 123.41 270 bottom
C3929  VALUE*  [M-C0402]  87.55 126.9 90 bottom
C3930  VALUE*  [M-C0603]  25.82 102.71 270 top
C3931  VALUE*  [M-C0603]  31.54 113.31 270 bottom
C3932  VALUE*  [M-C0603]  26.59 93.56 90 bottom
C3933  VALUE*  [M-C0603]  40.37 98.77 180 bottom
C3934  VALUE*  [M-C0402]  24.72 100 270 bottom
C3935  VALUE*  [M-C0402]  110.91 130.2 270 top
C3936  VALUE*  [M-C0603]  30.88 82.22 0 top
C3937  VALUE*  [M-C0603]  25.51 91.53 90 top
C3938  VALUE*  [M-C0402]  112.12 130.2 270 top
C3939  VALUE*  [M-C0402]  113.33 130.2 270 top
C3940  VALUE*  [M-C0402]  114.53 130.2 270 top
C3945  VALUE*  [M-C0603]  25.1 103.62 0 bottom
CN1  -  [CON_51625-18P_ACES]  17.12 62.12 180 bottom
CN3  3H125_3802K-F03N-01L_ENTERY  [CON_WB_3H125_85204-03001_ACES]  5 109.35 0 top
CN4  6916K-Q06N-07L  [CON_6916K-Q06N-07L]  6.63 42.25 270 top
CN5  @WB,ET,3802K-Q02N-01L,2P,SMT,P1.25  [CON_WB_2H125_85204-02001_ACES]  133.82 121.99 0 top
CN6  @WB-6H80_88460-0601_ACES  [CON_WB-6H80_88460-06001_ACES]  124.7 5 180 bottom
CN7  CON_FFC_40R05_S_50506_ACES  [CON_FFC_6712K-X40N-07X]  133.19 128.7 180 top
CN8  -  [CON_WB_10H80_S-88460-1001_ACES]  20.63 83.42 270 bottom
CN9  -  [CON22_1D27_HDD_TBF0]  -1.43 82.5 270 top
CN11  -  [DDR4_SODIMM_REV_260PIN_H5P2MM]  49.47 118.83 0 top
CN13  -  [TF_M2_KEY-B_2280_3H]  18.46 24.18 90 top
CN14  -  [TF_M2_KEY-E_2230_3H]  84.1 5.61 0 top
CN33  FFC,2P,SMT,P0.5,FP201CH-004M10M,JXT  [CON2-2_50278-002XX-ACES]  124.5 2.51 0 top
CRDR1  -  [CON_1IN1-R-NPS_DSD2-B_TAISOL]  142.79 36.55 90 top
CRDR2  @CON_1IN1-R-PS_CS2001_ATE  [CON_1IN1-R-PS_CS2001_ATE]  157.49 36.65 0 top
D1  -  [SK34A]  17.82 87.64 0 top
D4  -  [M-SOT23]  130.77 110.23 90 top
D6  -  [4148_WSP_0805]  135.4 121.47 270 bottom
D7  @Diode-AZ5315-02F  [DIODE-AZ5315-02F]  139.65 41.58 180 top
D8  @Diode-AZ5315-02F  [DIODE-AZ5315-02F]  139.47 28.48 270 top
D9  @Diode-AZ5315-02F  [DIODE-AZ5315-02F]  144.8 116.11 90 top
D10  @Diode-AZ5315-02F  [DIODE-AZ5315-02F]  145.11 113.35 270 top
D11  @Diode-AZ5315-02F  [DIODE-AZ5315-02F]  145.04 77.29 270 top
D12  @Diode-AZ5315-02F  [DIODE-AZ5315-02F]  145.49 59.19 270 top
D13  @Diode-AZ5315-02F  [DIODE-AZ5315-02F]  145.13 118.25 270 top
D14  @AZ5325-01F  [D0402_AC]  147.11 22.74 180 top
D15  -  [M-SOT23]  148.76 106.31 90 bottom
D16  -  [4148_WSP_0805]  16.68 99.45 0 bottom
D17  -  [4148_WSP_0805]  20.7 99.42 180 bottom
D18  -  [4148_WSP_0805]  16.43 89.92 180 bottom
D19  -  [M-SOT23]  14.98 80.07 270 bottom
D20  @AZ5325-01F  [D0402_AC]  156.61 24.08 0 bottom
D21  @AZ5325-01F  [D0402_AC]  157.78 11.56 270 bottom
D23  -  [SOD_123_2D0]  4.67 95 90 top
D26  -  [4148_WSP_0805]  34.81 48.84 180 top
D34  -  [4148_WSP_0805]  34.76 42.15 180 top
D41  -  [4148_WSP_0805]  37.99 53.39 0 bottom
D42  -  [4148_WSP_0805]  33.11 58.15 90 top
DCIN1  DCIN_WO_2DC3003-002211_SIN  [POWERJACK_W059]  155.81 130.9 90 top
EC1  @.1U-10-04R-K  [M-C0402]  143.79 66.73 180 top
EC2  @.1U-10-04R-K  [M-C0402]  44.01 119.88 90 top
ED3  @AZ5325-01F.R7G  [D0402]  136.32 17.66 180 top
ED4  @AZ5325-01F.R7G  [D0402]  137.97 18.8 180 top
ED5  @AZ5325-01F.R7G  [D0402]  140.51 18.55 180 top
ED6  @AZ5325-01F.R7G  [D0402]  143.43 18.04 0 top
ER1  499-1-04  [M-R0402]  138.88 126.47 270 bottom
ER2  499-1-04  [M-R0402]  136.7 126.5 270 bottom
H1  -  [TC296BC236D118]  2.69 55.3 0 top
H2  -  [TC296BC236D118]  14.19 137.3 0 top
H3  -  [TC276BC236D165]  37.08 76.48 0 top
H4  -  [TC296BC236D118]  41.19 34.2 0 top
H5  -  [TC296BC236D118]  65.84 137.3 0 top
H6  -  [TC276BC236D165]  114.12 65.68 0 top
H7  -  [TC276BC236D165]  114.12 87.27 90 top
H8  -  [TC296BC236D118]  135.19 37.8 90 top
H9  -  [HOLEO312X300DO132X120]  146.15 87.74 0 top
H10  -  [TC296BC236D118]  152.19 9.3 0 top
H11  -  [C197D87]  157.49 138.3 0 top
H24  -  [HOLEC276BC166D146]  98.19 24.2 0 top
HDMI1  HDMI-A-R_HAR01-191CN5V_H.T.  [CON19-4_0D5_0D55_HDMI_SA0127]  152.16 96.7 90 top
JP10  -  [TOPOPEN-157X20]  55.19 36.33 270 top
JP11  -  [TOPOPEN_20X30]  97.45 94.5 270 bottom
JP12  -  [TOPOPEN_20X30]  97.45 93.48 270 bottom
JP13  -  [TOPOPEN-157X20]  23.19 74.18 180 top
JP14  -  [TOPOPEN-157X20]  69.8 38.62 90 top
JP17  -  [TOPOPEN-157X20]  48.54 134.73 0 top
KBT1  FFC_24R10_6916K-Y24N_ENTRY  [CON24-2_1D0_DYS_W058]  5.67 125.64 270 top
L1  -  [CHOKE-7X7_8X3_5]  15.09 81.28 90 top
L2  -  [CHOKE-7X7_8X3_5]  33.7 134.5 270 top
L7  -  [CHOKE-7X7_8X3_5]  87.42 134.12 90 top
L8  -  [CHOKE-7X7_8X3_5]  94.15 44.46 0 top
L9  -  [CHOKE-7X7_8X3_5]  124.86 108 0 top
L11  -  [CHOKE-4P_2X1_2X1_2]  142.92 123.03 90 top
L12  -  [CHOKE-4P_2X1_2X1_2]  142.65 116.11 180 top
L13  -  [CHOKE-4P_2X1_2X1_2]  145.21 123.03 90 top
L14  -  [CHOKE-4P_2X1_2X1_2]  142.56 113.18 180 top
L16  -  [CHOKE-4P_2X1_2X1_2]  142.92 59.41 180 top
L17  -  [CHOKE-4P_2X1_2X1_2]  142.65 118.22 180 top
L18  -  [CHOKE-4P_2X1_2X1_2]  147.75 101.48 0 top
L19  -  [CHOKE-4P_2X1_2X1_2]  147.75 98.56 0 top
L20  -  [CHOKE-4P_2X1_2X1_2]  147.87 96.02 0 top
L21  -  [CHOKE-4P_2X1_2X1_2]  147.87 93.48 0 top
L23  -  [WSRPG0402-1R0M-H]  54.57 131.94 180 top
L25  -  [CHOKE-4P_2X1_2X1_2]  111.1 41.69 270 bottom
L26  -  [CHOKE-7X7_8X3_5]  77.51 41.66 0 top
L27  -  [CHOKE-7X7_8X3_5]  64.05 43.7 180 top
L28  -  [CHOKE-7X7_8X3_5]  42.77 62.1 90 top
L29  -  [CHOKE-4P_2X1_2X1_2]  141.31 78.93 180 top
L31  -  [CHOKE-7X7_8X3_5]  51.38 47 90 top
L32  -  [CHOKE-4P_2X1_2X1_2]  6.42 64.58 0 top
L49  -  [CHOKE-4P_2X1_2X1_2]  81.1 12.07 0 top
LED1  -  [LED_19-223_S2T1D-C30_2T]  117.64 133.14 270 bottom
LED2  -  [19-113]  111.89 133.14 270 bottom
LED3  -  [19-113]  105.69 133.14 270 bottom
LID1  -  [M-SOT23-3L]  157.78 27.31 180 bottom
